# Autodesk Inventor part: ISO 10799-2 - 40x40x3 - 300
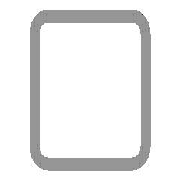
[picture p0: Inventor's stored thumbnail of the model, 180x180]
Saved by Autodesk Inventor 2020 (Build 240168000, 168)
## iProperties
Created: 2019-01
Part Number: ISO 10799-2 - 40x40x3 - 300
Material: Ocel
Description: Konstrukční oceli – za studena tvarované, svařované, stavební duté profily
Document SubType Name: Modeling
Standard: ISO 10799-2
Designer: doma
Standard Revision: First edition 2011-09-15
Standards Organization: ISO
Language: cs-CZ
Size Designation: 40x40x3 - 300
Categories: <MemberInstance><Categories><Category DisplayName="Konstrukční profily" InternalName="089c4875-fa83-4c05-b084-43b9cc11f5ed" Mnemonic="GRDR"><CategoryParameter D
Stock Number: 40x40x3
Density: 7.85 g/cm^3
Appearance: Plech
Mass: 982.998 g
Surface Area: 847.538 cm^2
Volume: 125.223 cm^3
IsCustomPart: 1
G_L: 300,000 mm
Author: doma
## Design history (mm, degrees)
node "Počáteční rovina"
node "Koncová rovina"
sketch "Náčrt"
  geometry: L1 (-20, -14)-(-20, 14); L2 (-14, 20)-(14, 20); L3 (20, 14)-(20, -14); L4 (14, -20)-(-14, -20); L5 (-14, 17)-(14, 17); L6 (17, 14)-(17, -14); L7 (14, -17)-(-14, -17); L8 (-17, -14)-(-17, 14); L9 (0, 37.102)-(0, -37.102) reference; L10 (-23.102, 0)-(23.102, 0) reference; A1 r 6 centre (-14, -14) between (-20, -14) and (-14, -20); A2 r 6 centre (14, 14) between (20, 14) and (14, 20); A3 r 6 centre (-14, 14) between (-14, 20) and (-20, 14); A4 r 6 centre (14, -14) between (14, -20) and (20, -14); A5 r 3 centre (-14, 14) between (-14, 17) and (-17, 14); A6 r 3 centre (14, 14) between (17, 14) and (14, 17); A7 r 3 centre (14, -14) between (14, -17) and (17, -14); A8 r 3 centre (-14, -14) between (-17, -14) and (-14, -17)
  constraints: 16 end point, 16 point on circle, 8 centre point, 8 tangent, 4 parallel, 3 equal radius, 2 perpendicular, 7 other
  dimensions: "d7" = 6 radius of A1 (= G_IR); "d9" = 40 distance between parallel lines of L1 L3 (= G_W); "d11" = 40 distance between parallel lines of L2 L4 (= G_H); "d12" = 3 distance between parallel lines of L3 L6 (= G_T); "d15" = 20 distance between parallel lines of L9 L3 (= 0.5 x d9); "d16" = 20 distance between parallel lines of L2 L10 (= 0.5 x d11)
extrude "Těleso" new body sketch "Náčrt" stored distance "d3" = 300 (= G_L); taper "d4" = 0 deg
node "Driven Length"
  sketch "Sketch3"
    geometry: L1 (0, 0)-(10, 0) reference
    constraints: 2 end point, 1 horizontal
  workplane "Work Plane3"
  sketch "Sketch4"
    geometry: L1 (-2, 0)-(12, 0) reference; L2 (-2, 300)-(12, 300) reference
    dimensions: "d18" = 300 distance between parallel lines of L1 L2 (derived)
sketch "Náčrt5"
  geometry: L1 (300, -28)-(300, 0) reference; L2 (300, -14)-(280, -14); C1 r 6.5 at (280, -14); 1 further point
  constraints: 2 end point, 1 centre point, 1 coincident, 1 horizontal, 1 midpoint
  dimensions: "d19" = 20 distance of L2.start L2.end; "d20" = 13 diameter of C1
extrude "Vysunutí2" cut sketch "Náčrt5" extent not by distance; stored distance "d21" = 0; taper "d22" = 0 deg
sketch "Náčrt7"
  geometry: L1 (300, 28)-(300, 0) reference; L2 (300, 34)-(0, 34) reference; L3 (300, -6)-(0, -6) reference; 3 further points
  dimensions: "d36" = 15 distance from line of point (285, 27) L1; "d46" = 13 vertical distance of point (285, 27) point (300, 14); "d47" = 13 vertical distance of point (285, 1) point (300, 14) (= d46)
hole "Díra2" sketch "Náčrt7" at (285, 1), (285, 27) diameter "d39" = 3; stored, may be unused: countersink angle "d43" = 90 deg, drill point angle "d45" = 118 deg; dims "d40" = 6, "d41" = 20, "d42" = 12, "d44" = 20
body "Solid1"
other parameters: "G_W" = 40 [user parameter; used in 1 equation term], "G_H" = 40 [user parameter; used in 1 equation term], "G_T" = 3 [user parameter; used in 1 equation term], "G_IR" = 6 [user parameter; used in 1 equation term], "G_L" = 300 (= d18) [user parameter; used in 1 equation term], "G_OFFSET_START" = 0 [user parameter; used in 1 equation term], "G_OFFSET_END" = 0 [user parameter; used in 1 equation term], "d13" = 0 (computed from G_OFFSET_START), "d17" = 90 deg, "MAS" = 0.33 [user parameter]
